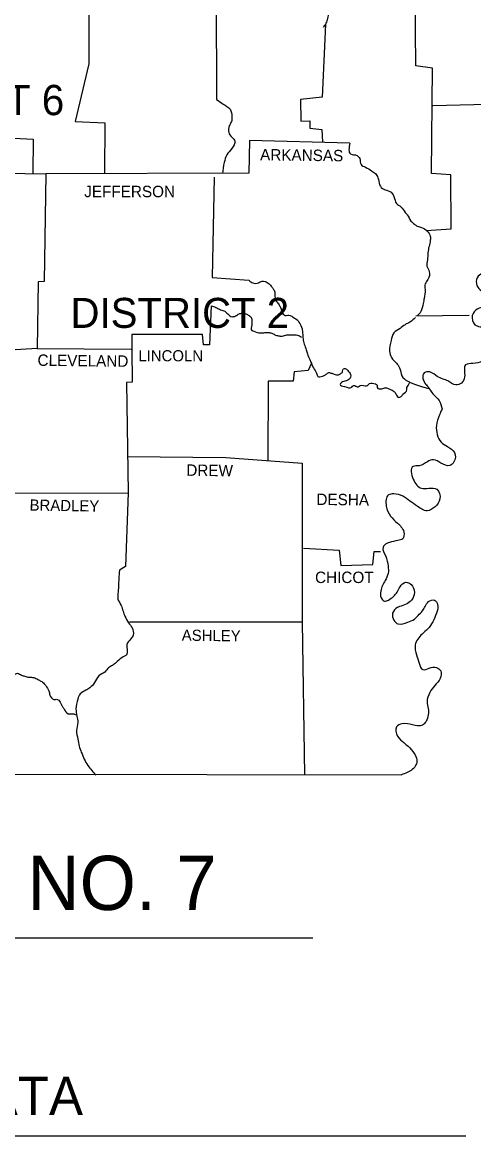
# Model space of a CAD drawing. Extents: x 1373094 to 1376427, y 1168361 to 1170494.
# Drawn here: x 1375995.2 to 1376172.6, y 1169546.2 to 1169984 of the extents above; entities that cross this region are included whole.
import ezdxf

# ---------------------------------------------------------------- set-up
doc = ezdxf.new("R2010")
doc.units = 0
doc.layers.add('Default', color=7, linetype='Continuous')
doc.layers.add('R_Draft', color=7, linetype='Continuous')

msp = doc.modelspace()

# ---------------------------------------------------------------- linework, layer by layer
at = {"layer": 'Default'}
for p, q in [((1376149.94, 1169868.58), (1376170.83, 1169868.89)), ((1375781.58, 1169624.07), (1376109.43, 1169624.07))]:
    msp.add_line(p, q, dxfattribs=at)
for points in [[(1376056.5, 1170012.77), (1376056.7, 1169994.08), (1376071.43, 1169993.76), (1376071.53, 1169953.67)], [(1376015.25, 1170007.96), (1376021.31, 1170007.55), (1376021.41, 1169967.66), (1376015.98, 1169945), (1376027.57, 1169944.48), (1376027.47, 1169924.53)], [(1376153.99, 1169902.2), (1376163.73, 1169902.82), (1376163.62, 1169924.02), (1376156, 1169924.54), (1376156.42, 1169965.99), (1376149.84, 1169966.93), (1376149.63, 1169994.81), (1376238.69, 1169995.43)], [(1375933.92, 1169981.91), (1375946.34, 1169981.13), (1375945.92, 1169968.08), (1375959.6, 1169967.56), (1375959.81, 1169956.18), (1375966.28, 1169955.65), (1375966.28, 1169953.67), (1375972.34, 1169953.25), (1375972.55, 1169945.94), (1375986.33, 1169945.94), (1375986.75, 1169938.74), (1375999.49, 1169938.11), (1375999.38, 1169924.52)], [(1376114.34, 1169983.22), (1376113.09, 1169954.61), (1376104.53, 1169953.67), (1376104.73, 1169945.21), (1376108.18, 1169945.32), (1376108.28, 1169942.39), (1376112.98, 1169941.87), (1376113.14, 1169936.83)], [(1376156.63, 1169951.27), (1376215.52, 1169952.73)], [(1376123.95, 1169936.55), (1376084.48, 1169937.59), (1376084.27, 1169924.75), (1376004.4, 1169924.44)], [(1375944.25, 1169910.65), (1375950.1, 1169911.49), (1375950.52, 1169915.04), (1375953.96, 1169915.66), (1375954.17, 1169917.75), (1375978.5, 1169918.48), (1375979.44, 1169924.85), (1376004.39, 1169924.44)], [(1376004.4, 1169924.44), (1376003.77, 1169882.05), (1376001.37, 1169881.94), (1376001.05, 1169855.73)], [(1376070.59, 1169923.08), (1376069.76, 1169883.72), (1376084.27, 1169882.57)], [(1376069.44, 1169872.54), (1376068.82, 1169857.2), (1376066.42, 1169857.2), (1376066, 1169861.27), (1376038.22, 1169861.27), (1376038.26, 1169855.52)], [(1376001.05, 1169855.73), (1375985.79, 1169854.79)], [(1376001.05, 1169855.73), (1376038.02, 1169855.53)], [(1376038.26, 1169855.52), (1376038.33, 1169842.47), (1376036.14, 1169842.37), (1376036.76, 1169799.04)], [(1376108.81, 1169849.99), (1376107.55, 1169847.17), (1376102.02, 1169846.65), (1376101.71, 1169842.89), (1376091.79, 1169842.89), (1376091.68, 1169811.67)], [(1376147.44, 1169842.58), (1376149.78, 1169841.66), (1376152.46, 1169840.73), (1376155, 1169840.08)], [(1376036.45, 1169813.24), (1376075.19, 1169812.93), (1376105.26, 1169810.63)], [(1376105.26, 1169810.63), (1376105.26, 1169748.19), (1376106.09, 1169688.16)], [(1375989.57, 1169798.94), (1376036.76, 1169799.04)], [(1376036.76, 1169799.04), (1376035.72, 1169770.01), (1376033.42, 1169768.55)], [(1376105.78, 1169777.32), (1376119.77, 1169776.49), (1376120.4, 1169770.43), (1376133.03, 1169770.85), (1376133.55, 1169775.97), (1376135.95, 1169775.97)], [(1375761.32, 1169773.25), (1375761.53, 1169688.78), (1376144.2, 1169688.16)], [(1376037.39, 1169748.3), (1376105.26, 1169748.3)]]:
    msp.add_lwpolyline(points, dxfattribs=at)
for points in [[(1376113.19, 1169993.24), (1376112.77, 1169991.15), (1376113.61, 1169988.96), (1376115.07, 1169988.23), (1376115.28, 1169986.14), (1376114.76, 1169984.05), (1376114.34, 1169983.22), (1376113.4, 1169981.96)], [(1376232.12, 1169970.17), (1376229.72, 1169967.14), (1376226.17, 1169969.02), (1376226.17, 1169971.52), (1376226.69, 1169974.13), (1376225.43, 1169975.8), (1376223.24, 1169975.07), (1376223.24, 1169971.84), (1376223.03, 1169968.7), (1376222.41, 1169964.22), (1376223.87, 1169962.86), (1376227.21, 1169962.44), (1376229.61, 1169961.81), (1376231.07, 1169959.41), (1376230.97, 1169956.49), (1376229.82, 1169953.67), (1376228.15, 1169951.37), (1376225.54, 1169950.54), (1376223.45, 1169951.89), (1376222.62, 1169954.61), (1376221.68, 1169957.01), (1376219.9, 1169958.79), (1376218.02, 1169956.8), (1376217.6, 1169953.15), (1376217.71, 1169950.02), (1376217.71, 1169945.73), (1376220.42, 1169942.92), (1376222.09, 1169939.68), (1376221.57, 1169936.76), (1376219.59, 1169933.31), (1376218.75, 1169930.28), (1376217.92, 1169926.21), (1376218.02, 1169921.72), (1376217.29, 1169917.34), (1376215.83, 1169914.41), (1376213.11, 1169912.01), (1376211.34, 1169910.44), (1376209.88, 1169908.88), (1376209.15, 1169905.75), (1376208.62, 1169903.55), (1376206.64, 1169900.94), (1376205.07, 1169900.73), (1376203.82, 1169901.78), (1376203.4, 1169903.55), (1376203.4, 1169905.33), (1376202.57, 1169907.1), (1376199.96, 1169907.83), (1376197.87, 1169907.73), (1376196.93, 1169906.27), (1376198.29, 1169902.2), (1376198.81, 1169899.59), (1376198.08, 1169896.04), (1376198.5, 1169895.62), (1376194.74, 1169893.63), (1376191.71, 1169893.32), (1376189.2, 1169892.59), (1376186.8, 1169891.02), (1376185.65, 1169888.73), (1376183.98, 1169886.85), (1376182.52, 1169885.07), (1376180.54, 1169884.24), (1376178.34, 1169884.66), (1376175.42, 1169884.97), (1376173.75, 1169882.88), (1376174.27, 1169879.85), (1376176.26, 1169878.08), (1376179.18, 1169877.24), (1376182.21, 1169877.45), (1376185.13, 1169877.76), (1376187.85, 1169876.3), (1376187.32, 1169873.48), (1376184.71, 1169872.13), (1376180.85, 1169871.71), (1376177.72, 1169872.02), (1376173.96, 1169871.19), (1376172.08, 1169868.79), (1376173.12, 1169865.13), (1376177.2, 1169863.67), (1376179.08, 1169860.22), (1376179.18, 1169856.99), (1376177.82, 1169852.71), (1376175.94, 1169850.72), (1376172.29, 1169849.89), (1376169.47, 1169849.36), (1376169.05, 1169844.56), (1376167.8, 1169842.16), (1376165.61, 1169841.43), (1376162.47, 1169843), (1376160.59, 1169843.73), (1376158.3, 1169844.77), (1376155.37, 1169846.55), (1376153.18, 1169846.23), (1376153.81, 1169841.64), (1376154.02, 1169841.43), (1376156.52, 1169837.98), (1376159.03, 1169835.27), (1376160.18, 1169832.03)], [(1376071.53, 1169953.67), (1376074.14, 1169951.89), (1376076.86, 1169949.81), (1376077.59, 1169946.99), (1376077.38, 1169945), (1376076.54, 1169943.33), (1376076.33, 1169940.72), (1376077.59, 1169938.84), (1376078.74, 1169937.28), (1376077.59, 1169934.46), (1376075.6, 1169931.85), (1376074.56, 1169928.92), (1376073.83, 1169924.54)], [(1376123.95, 1169936.55), (1376124.26, 1169932.27), (1376126.77, 1169931.64), (1376127.81, 1169930.49), (1376128.33, 1169928.09), (1376130.11, 1169927.05), (1376132.51, 1169925.58), (1376133.97, 1169924.54), (1376135.01, 1169922.87), (1376135.64, 1169920.15), (1376137.31, 1169918.38), (1376139.61, 1169917.54), (1376141.28, 1169915.56), (1376142.32, 1169912.74), (1376143.99, 1169911.49), (1376145.66, 1169909.3), (1376146.5, 1169908.36), (1376147.96, 1169905.85), (1376149.42, 1169904.6), (1376150.47, 1169903.87), (1376152.14, 1169903.34), (1376154.23, 1169901.99), (1376155.58, 1169899.9), (1376155.58, 1169898.33), (1376155.06, 1169895.93), (1376154.64, 1169893.43), (1376154.43, 1169890.61), (1376154.23, 1169888.1), (1376155.17, 1169886.01), (1376154.64, 1169882.88), (1376153.6, 1169881.21), (1376153.49, 1169878.91), (1376153.18, 1169875.47), (1376152.76, 1169873.48), (1376151.82, 1169870.25), (1376150.47, 1169868.58)], [(1376084.27, 1169882.57), (1376085.84, 1169881.52), (1376088.03, 1169881.63), (1376089.49, 1169882.25), (1376090.64, 1169882.15), (1376092.2, 1169881.21), (1376093.25, 1169879.96), (1376093.98, 1169879.02), (1376094.5, 1169877.56), (1376094.5, 1169876.2), (1376095.02, 1169874.32), (1376095.65, 1169873.59), (1376096.49, 1169872.23), (1376097.01, 1169870.98), (1376097.32, 1169870.14), (1376098.47, 1169868.79), (1376099.51, 1169868.89), (1376100.45, 1169868.79), (1376101.71, 1169868.05), (1376103.59, 1169866.59), (1376103.9, 1169866.17), (1376105.15, 1169863.46), (1376105.36, 1169861.79), (1376105.57, 1169859.6), (1376105.99, 1169857.51), (1376106.82, 1169855.21), (1376107.24, 1169853.65), (1376108.18, 1169851.45), (1376108.81, 1169849.99), (1376109.64, 1169848.11), (1376110.89, 1169846.02), (1376111.42, 1169844.77), (1376113.19, 1169844.88), (1376114.44, 1169845.4), (1376115.38, 1169846.23), (1376116.53, 1169846.13), (1376117.79, 1169845.71), (1376119.46, 1169845.4), (1376120.5, 1169846.02), (1376121.02, 1169846.44), (1376121.13, 1169847.38), (1376122.07, 1169847.9), (1376123.11, 1169847.17), (1376124.26, 1169845.5), (1376124.26, 1169844.46), (1376123.84, 1169843.83), (1376122.48, 1169843), (1376120.6, 1169842.37), (1376120.08, 1169841.64), (1376121.86, 1169840.8), (1376124.68, 1169840.59), (1376125.41, 1169841.22), (1376127.29, 1169840.7), (1376128.02, 1169841.22), (1376130.52, 1169841.12), (1376131.67, 1169841.95), (1376133.97, 1169841.85), (1376134.7, 1169841.33), (1376134.7, 1169840.39), (1376136.58, 1169839.97), (1376137.94, 1169840.28), (1376139.71, 1169839.76), (1376141.28, 1169838.92), (1376142.11, 1169837.78), (1376143.16, 1169836.52), (1376144.1, 1169836.84), (1376144.83, 1169837.78), (1376146.39, 1169839.45), (1376146.39, 1169840.49), (1376146.81, 1169841.22), (1376147.33, 1169842.27)], [(1376069.44, 1169872.54), (1376071.32, 1169871.92), (1376072.68, 1169871.19), (1376074.45, 1169870.56), (1376075.6, 1169869.72), (1376077.17, 1169868.37), (1376079.05, 1169868.58), (1376080.41, 1169869.41), (1376081.76, 1169869.62), (1376082.81, 1169869.52), (1376083.96, 1169868.89), (1376085.21, 1169867.95), (1376085.42, 1169866.59), (1376085.42, 1169865.03), (1376085.42, 1169862.83), (1376086.15, 1169862.52), (1376088.76, 1169861.89), (1376090.53, 1169862), (1376092.2, 1169862), (1376093.56, 1169861.69), (1376094.71, 1169861.06), (1376095.55, 1169860.85), (1376096.8, 1169860.64), (1376097.84, 1169860.75), (1376099.62, 1169861.16), (1376100.66, 1169861.16), (1376102.33, 1169861.16), (1376103.38, 1169861.06), (1376104.94, 1169860.22)], [(1376149.74, 1169867.95), (1376147.54, 1169866.17), (1376145.66, 1169865.13), (1376143.68, 1169863.67), (1376141.28, 1169861.89), (1376140.13, 1169858.87), (1376139.5, 1169854.69), (1376140.34, 1169852.18), (1376142.22, 1169849.99), (1376143.47, 1169848.22), (1376144.41, 1169845.08), (1376146.71, 1169842.89), (1376147.44, 1169842.58)], [(1376160.18, 1169832.03), (1376159.13, 1169829.63), (1376157.98, 1169825.46), (1376158.3, 1169821.91), (1376159.86, 1169818.88), (1376162.37, 1169817.21), (1376165.08, 1169814.81), (1376164.88, 1169811.15), (1376163.31, 1169809.79), (1376159.65, 1169810.73), (1376156.84, 1169811.99), (1376154.43, 1169811.26), (1376151.2, 1169809.69), (1376148.8, 1169809.38), (1376148.9, 1169804.36), (1376152.14, 1169800.81), (1376154.96, 1169800.81), (1376158.19, 1169800.4), (1376159.34, 1169796.64), (1376157.46, 1169793.51), (1376154.33, 1169791.94), (1376150.36, 1169793.82), (1376147.54, 1169795.8), (1376144.72, 1169797.68), (1376141.17, 1169798.62), (1376139.19, 1169798.2), (1376138.25, 1169793.82), (1376139.92, 1169789.85), (1376142.64, 1169787.14), (1376145.14, 1169783.59), (1376144.72, 1169780.98), (1376142.84, 1169780.25), (1376139.5, 1169779.52), (1376137.52, 1169778.47), (1376137, 1169777.64), (1376138.04, 1169774.09), (1376138.98, 1169770.22), (1376138.98, 1169767.3), (1376137.83, 1169764.58), (1376136.06, 1169760.41), (1376136.27, 1169757.69), (1376137.52, 1169756.44), (1376139.09, 1169756.86), (1376141.17, 1169758.32), (1376142.53, 1169759.99), (1376143.68, 1169762.08), (1376145.87, 1169763.85), (1376148.59, 1169762.29), (1376149.21, 1169759.05), (1376147.65, 1169756.23), (1376145.45, 1169754.98), (1376142.74, 1169753.93), (1376140.76, 1169751.64), (1376141.28, 1169748.92), (1376142.84, 1169747.46), (1376146.71, 1169748.19), (1376149.32, 1169749.34), (1376150.78, 1169750.8), (1376152.55, 1169752.58), (1376153.49, 1169754.35), (1376154.85, 1169756.23), (1376157.25, 1169756.75), (1376158.4, 1169755.19), (1376157.98, 1169751.64), (1376156.52, 1169748.3), (1376154.54, 1169745.48), (1376152.35, 1169743.49), (1376149.63, 1169739.21), (1376150.15, 1169735.25), (1376151.2, 1169732.01), (1376152.66, 1169729.5), (1376155.17, 1169730.03), (1376157.98, 1169730.34), (1376159.65, 1169728.98), (1376159.45, 1169726.06), (1376157.36, 1169723.24), (1376155.37, 1169720.52), (1376154.33, 1169716.77), (1376154.75, 1169714.15), (1376154.75, 1169711.75), (1376153.91, 1169709.14), (1376152.45, 1169707.68), (1376148.59, 1169707.79), (1376144.52, 1169708.2), (1376142.32, 1169706.95), (1376142.74, 1169703.4), (1376145.14, 1169700.79), (1376146.81, 1169699.43), (1376149.21, 1169696.51), (1376150.26, 1169694.11), (1376149.94, 1169692.02), (1376148.48, 1169690.25), (1376144.2, 1169688.16)], [(1376033.42, 1169768.55), (1376033.11, 1169765.32), (1376033, 1169762.29), (1376032.79, 1169759.36), (1376032.79, 1169757.17), (1376034.05, 1169754.77), (1376034.78, 1169752.47), (1376035.51, 1169750.49), (1376036.97, 1169747.88), (1376038.33, 1169745.9), (1376038.75, 1169743.08), (1376037.91, 1169741.61), (1376036.34, 1169739.42), (1376036.24, 1169735.45), (1376034.36, 1169734.2), (1376031.96, 1169732.11), (1376030.6, 1169731.17), (1376029.14, 1169730.23), (1376027.57, 1169728.56), (1376025.28, 1169727), (1376023.61, 1169724.39), (1376021.73, 1169722.4), (1376020.16, 1169721.36), (1376017.97, 1169720), (1376017.03, 1169717.91), (1376016.3, 1169714.05), (1376016.61, 1169711.23), (1376017.03, 1169708.73), (1376016.51, 1169705.59), (1376017.03, 1169702.15), (1376017.55, 1169699.43), (1376018.39, 1169697.03), (1376019.53, 1169694.32), (1376021, 1169691.81), (1376024.13, 1169687.95)], [(1375929.32, 1169744.43), (1375930.99, 1169745.58), (1375932.56, 1169746.21), (1375934.13, 1169745.9), (1375935.8, 1169745.69), (1375937.26, 1169745.9), (1375939.14, 1169745.58), (1375940.7, 1169744.64), (1375942.48, 1169743.91), (1375944.25, 1169743.91), (1375945.82, 1169743.91), (1375947.18, 1169742.97), (1375949.68, 1169743.08), (1375951.77, 1169743.91), (1375953.86, 1169744.54), (1375956.68, 1169744.85), (1375959.18, 1169743.08), (1375960.96, 1169741.61), (1375962.42, 1169739.94), (1375963.47, 1169738.06), (1375964.61, 1169737.02), (1375966.49, 1169736.29), (1375967.95, 1169735.98), (1375969.73, 1169735.45), (1375970.67, 1169735.04), (1375971.5, 1169733.05), (1375972.86, 1169730.34), (1375975.47, 1169729.4), (1375978.71, 1169730.65), (1375981.32, 1169731.38), (1375983.2, 1169732.01), (1375984.35, 1169732.43), (1375985.39, 1169732.53), (1375985.08, 1169732.74), (1375986.33, 1169733.05), (1375987.48, 1169732.22), (1375988.21, 1169731.07), (1375989.46, 1169729.4), (1375990.61, 1169727.94), (1375991.76, 1169727.41), (1375992.91, 1169728.04), (1375994.48, 1169727.52), (1375995.83, 1169727), (1375997.4, 1169726.58), (1375998.76, 1169726.48), (1376000.53, 1169726.06), (1376001.89, 1169725.33), (1376003.14, 1169724.6), (1376004.39, 1169723.24), (1376005.65, 1169721.15), (1376006.07, 1169719.48), (1376007.53, 1169717.81), (1376008.88, 1169717.81), (1376010.87, 1169715.09), (1376011.6, 1169714.05), (1376013.17, 1169712.17), (1376014.31, 1169712.17), (1376016.51, 1169711.75)]]:
    msp.add_spline(points, degree=3, dxfattribs=at)
at = {"layer": 'R_Draft'}
msp.add_line((1375704.42, 1169546.23), (1376169.6, 1169546.23), dxfattribs=at)

# ---------------------------------------------------------------- texts
at = {"layer": 'Default'}
for s, height, p in [('DISTRICT 6', 11.903, (1375925.04, 1169947.51)), ('JEFFERSON', 4.49, (1376019.53, 1169915.25)), ('DISTRICT 2', 11.798, (1376014.15, 1169863.87)), ('LINCOLN', 4.385, (1376040.83, 1169850.72)), ('CHICOT', 4.49, (1376110.27, 1169763.54)), ('  ARK. HWY. DIST. NO. 7', 21.2995, (1375743.95, 1169634.99))]:
    msp.add_text(s, height=height, dxfattribs=at).set_placement(p)
for s, height, rotation, p in [('ARKANSAS', 4.489, 359.2678, (1376088.65, 1169929.76)), ('CLEVELAND', 4.49, 359.3377, (1376001.16, 1169848.95)), ('DREW', 4.489, 359.2258, (1376059.63, 1169805.72)), ('BRADLEY', 4.384, 359.1449, (1375998.03, 1169792.04)), ('DESHA', 4.489, 359.3704, (1376110.79, 1169794.24)), ('ASHLEY', 4.386, 359.2361, (1376057.85, 1169740.88))]:
    msp.add_text(s, height=height, rotation=rotation, dxfattribs=at).set_placement(p)
at = {"layer": 'R_Draft'}
msp.add_text('DESIGN TRAFFIC DATA', height=15, dxfattribs=at).set_placement((1375792.83, 1169554.39))

doc.saveas('drawing.dxf')
